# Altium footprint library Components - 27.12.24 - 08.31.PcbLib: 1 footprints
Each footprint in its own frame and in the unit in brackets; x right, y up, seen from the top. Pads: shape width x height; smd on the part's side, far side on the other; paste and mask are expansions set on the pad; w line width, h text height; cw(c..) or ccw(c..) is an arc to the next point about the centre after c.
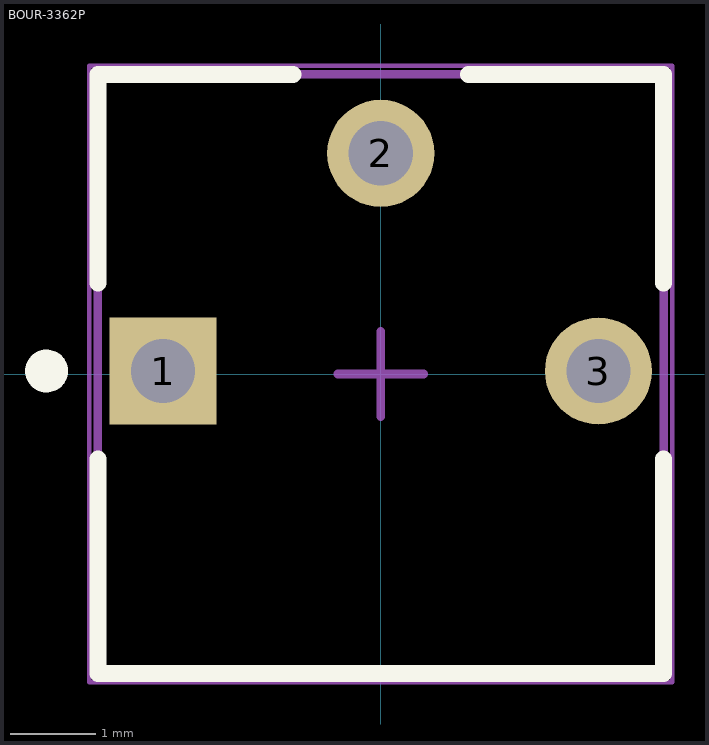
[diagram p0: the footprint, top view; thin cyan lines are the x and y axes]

## BOUR-3362P [mm] "THD, 3-Leads, Body 6.6x6.99mm, Pitch 2.54mm"
height 4.95
pads (3):
  rect 1.25x1.25 hole 0.75: 1(-2.54,0.035)
  round 1.25 hole 0.75: 2(0,2.575) 3(2.54,0.035)
Top Overlay:
  circle w0.25: c-3.9,0.035 r0.125
  lines w0.2: -3.3,-0.99 -3.3,-3.495 3.3,-3.495 3.3,-0.99 ; -3.3,1.06 -3.3,3.495 -1.025,3.495 ; 1.025,3.495 3.3,3.495 3.3,1.06
Mechanical 13:
  lines w0.1: -3.3,-3.495 -3.3,3.495 3.3,3.495 3.3,-3.495 -3.3,-3.495
Mechanical 15:
  lines w0.05: -3.4,-3.595 3.4,-3.595 3.4,3.595 -3.4,3.595 -3.4,-3.595
  lines w0.1: -0.5,0 0.5,0 ; 0,-0.5 0,0.5
3D body: height 4.95, standoff 0, extent -3.299,-3.494 3.299,3.494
